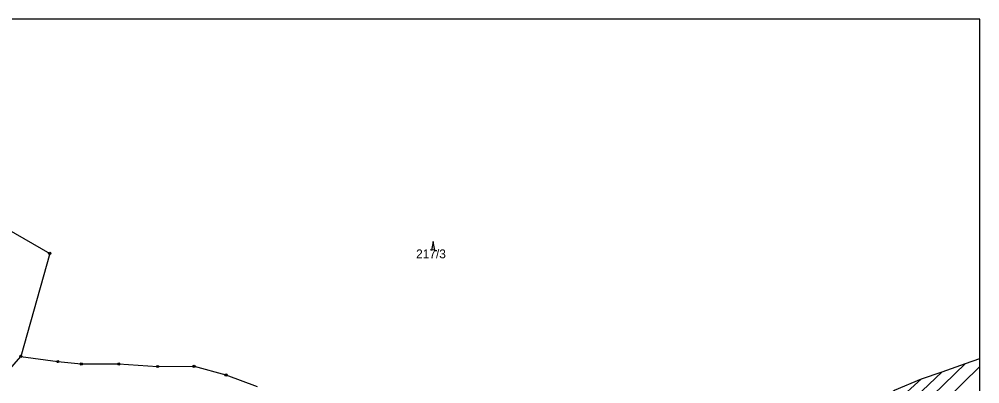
# Model space of a CAD drawing. Extents: x -564516 to -563466, y -1163913 to -1163170.
# Drawn here: x -563898.7 to -563466.4, y -1163334.3 to -1163170 of the extents above; entities that cross this region are included whole.
import ezdxf

# ---------------------------------------------------------------- set-up
doc = ezdxf.new("R2010")
doc.units = 0
for name, color, linetype in [('_parcely přehledka', 7, 'Continuous'), ('Hranice parcel', 7, 'Continuous'), ('Obvod PU', 7, 'Continuous'), ('Parcelní čísla', 7, 'Continuous'), ('Značky bodu BP', 7, 'Continuous'), ('Značky kultur', 7, 'Continuous')]:
    doc.layers.add(name, color=color, linetype=linetype)

msp = doc.modelspace()

# ---------------------------------------------------------------- linework, layer by layer
at = {"layer": '_parcely přehledka'}
msp.add_line((-563466.35, -1163170.03), (-564516.35, -1163170.03), dxfattribs=at)
msp.add_lwpolyline([(-564516.35, -1163170.03), (-564516.35, -1163912.53), (-563466.35, -1163912.53), (-563466.35, -1163170.03)], dxfattribs=at)
at = {"layer": 'Hranice parcel'}
for points in [[(-563920.13, -1163255.3), (-563884.9, -1163275.51), (-563897.93, -1163321.91)], [(-563946.81, -1163394.51), (-563921.02, -1163350.78), (-563912.02, -1163338.09), (-563897.93, -1163321.91)], [(-563897.93, -1163321.91), (-563881.27, -1163324.26), (-563870.72, -1163325.36), (-563853.83, -1163325.33), (-563836.35, -1163326.49), (-563819.97, -1163326.37), (-563805.63, -1163330.27), (-563791.55, -1163335.5)], [(-563472.82, -1163325.1), (-563492.4, -1163344.19), (-563563.12, -1163409.18), (-563578.9, -1163425.55), (-563599.71, -1163447.94), (-563619.51, -1163469.95), (-563641.92, -1163497.36), (-563657.79, -1163516.57), (-563674.09, -1163534.63), (-563706.73, -1163569.48), (-563730.65, -1163592.66), (-563738.15, -1163601.56), (-563747.8, -1163615.9), (-563755.42, -1163627.59), (-563760.64, -1163636.71), (-563766.24, -1163646.94), (-563768.37, -1163652.1)], [(-563483.32, -1163328.82), (-563498.3, -1163343.11), (-563559.5, -1163398.24), (-563581.3, -1163420.87), (-563602.34, -1163443.09), (-563626.81, -1163470.77), (-563647.88, -1163496.75), (-563660.04, -1163511.31), (-563676.05, -1163529.51), (-563701.44, -1163556.83), (-563716.72, -1163573.04), (-563732.31, -1163588.43), (-563737.4, -1163593.77), (-563742.55, -1163600.35), (-563759.04, -1163625.53), (-563764.01, -1163633.9), (-563769.07, -1163642.98), (-563773.69, -1163652.01)], [(-563466.35, -1163326.54), (-563481.91, -1163341.79), (-563503.39, -1163361.7), (-563547.11, -1163402.34), (-563568.21, -1163422.97), (-563585.7, -1163441.32), (-563598.54, -1163455.13), (-563615.18, -1163473.64), (-563641.36, -1163506.22), (-563651.94, -1163518.83), (-563666.9, -1163535.69), (-563692.99, -1163562.42), (-563722.34, -1163590.39), (-563729.59, -1163598.52), (-563734.31, -1163604.94), (-563752.39, -1163632.21), (-563757.45, -1163640.46), (-563763.4, -1163652.18)], [(-563492.6, -1163332.11), (-563503.83, -1163342.23), (-563543.19, -1163374.77), (-563566.39, -1163396.02), (-563581.06, -1163411.4), (-563611.4, -1163444.26), (-563633.36, -1163469.72), (-563656.32, -1163498.04), (-563671.96, -1163517.15), (-563698.7, -1163546.56), (-563722.03, -1163572.73), (-563739.26, -1163589.69), (-563745.02, -1163596.95), (-563756.14, -1163612.7), (-563762.32, -1163621.9), (-563768.98, -1163633.06), (-563774.53, -1163643.02), (-563778.72, -1163651.64)]]:
    msp.add_lwpolyline(points, dxfattribs=at)
at = {"layer": 'Obvod PU'}
for p, q in [((-563483.32, -1163328.82), (-563472.82, -1163325.1)), ((-563483.32, -1163328.82), (-563472.82, -1163325.1)), ((-563472.82, -1163325.1), (-563466.35, -1163322.81)), ((-563472.82, -1163325.1), (-563466.35, -1163322.81)), ((-563492.6, -1163332.11), (-563483.32, -1163328.82)), ((-563492.6, -1163332.11), (-563483.32, -1163328.82))]:
    msp.add_line(p, q, dxfattribs=at)
msp.add_lwpolyline([(-563543.33, -1163366.56), (-563504.72, -1163337.08), (-563492.6, -1163332.11)], dxfattribs=at)
msp.add_lwpolyline([(-563543.33, -1163366.56), (-563504.72, -1163337.08), (-563492.6, -1163332.11)], dxfattribs=at)
at = {"layer": 'Značky bodu BP'}
for centre, radius in [((-563884.9, -1163275.51), 0.5), ((-563884.9, -1163275.51), 0.0303), ((-563897.93, -1163321.91), 0.5), ((-563897.93, -1163321.91), 0.0303), ((-563881.27, -1163324.26), 0.5), ((-563881.27, -1163324.26), 0.0303), ((-563870.72, -1163325.36), 0.5), ((-563870.72, -1163325.36), 0.0303), ((-563853.83, -1163325.33), 0.5), ((-563853.83, -1163325.33), 0.0303), ((-563836.35, -1163326.49), 0.5), ((-563836.35, -1163326.49), 0.0303), ((-563819.97, -1163326.37), 0.5), ((-563819.97, -1163326.37), 0.0303), ((-563805.63, -1163330.27), 0.5), ((-563805.63, -1163330.27), 0.0303)]:
    msp.add_circle(centre, radius, dxfattribs=at)
at = {"layer": 'Značky kultur'}
for p, q in [((-563712.4, -1163270.21), (-563713.15, -1163274.21)), ((-563711.65, -1163274.21), (-563712.4, -1163270.21)), ((-563711.65, -1163274.21), (-563710.65, -1163274.21))]:
    msp.add_line(p, q, dxfattribs=at)

# ---------------------------------------------------------------- texts
at = {"layer": 'Parcelní čísla'}
msp.add_text('217/3', height=4, dxfattribs=at).set_placement((-563720.03, -1163277.76))

doc.saveas('drawing.dxf')
